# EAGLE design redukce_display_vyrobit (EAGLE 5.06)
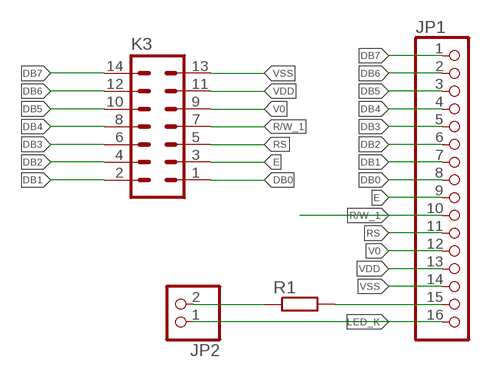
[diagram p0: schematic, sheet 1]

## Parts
JP1  PINHD-1X16  [1X16]
JP2  PINHD-1X2  [1X02]
K3  14V  [14V]
R1  R-EU_0207/10  [0207/10]

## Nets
DB0: JP1.8 K3.1
DB1: JP1.7 K3.2
DB2: JP1.6 K3.4
DB3: JP1.5 K3.6
DB4: JP1.4 K3.8
DB5: JP1.3 K3.10
DB6: JP1.2 K3.12
DB7: JP1.1 K3.14
E: JP1.9 K3.3
LED_K: JP1.16 JP2.1
N$1: JP2.2 R1.1
N$2: JP1.15 R1.2
R/W_1: JP1.10 K3.7
RS: JP1.11 K3.5
V0: JP1.12 K3.9
VDD: JP1.13 K3.11
VSS: JP1.14 K3.13

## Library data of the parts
JP1 = pinhead:PINHD-1X16: PIN HEADER
JP2 = pinhead:PINHD-1X2: PIN HEADER
K3 = con-harting-v:14V: CONNECTOR
R1 = rcl:R-EU_: RESISTOR, European symbol

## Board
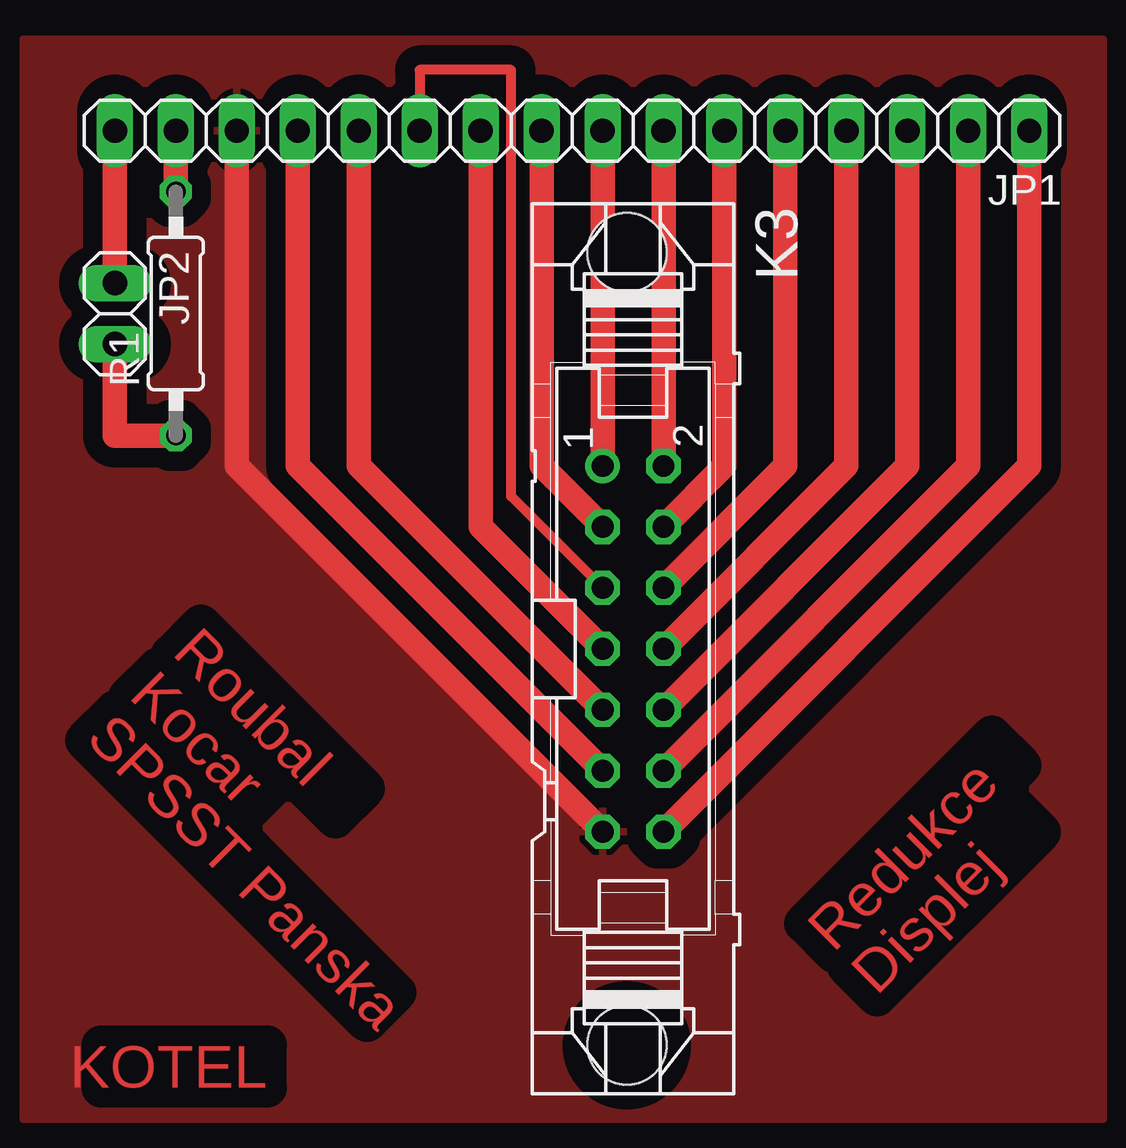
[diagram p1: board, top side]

No outline drawn. Coordinates in mm, seen from the top.
Copper layers (1*16): Top 0.035mm / dielectric 1.5mm / Bottom 0.035mm
Design rules "default": minimum track width 10mil, minimum drill 24mil, track to track 8mil, track to pad 8mil, pad to pad 8mil, via to via 8mil, smd to smd 8mil, copper to edge 40mil, drill to drill 8mil, minimum pad ring 10mil, minimum via ring 8mil, stop-mask expansion 4mil, vias tented up to drill 0mil, thermal gap 10mil

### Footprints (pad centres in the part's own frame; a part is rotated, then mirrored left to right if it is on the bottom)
1X16 = drill 1.016 long: 1 -19.05,0; 2 -16.51,0; 3 -13.97,0; 4 -11.43,0; 5 -8.89,0; 6 -6.35,0; 7 -3.81,0; 8 -1.27,0; 9 1.27,0; 10 3.81,0; 11 6.35,0; 12 8.89,0; 13 11.43,0; 14 13.97,0; 15 16.51,0; 16 19.05,0
1X02 = drill 1.016 long: 1 -1.27,0; 2 1.27,0
14V = drill 0.914 round: 1 -7.62,-1.27 | drill 0.914 octagon: 2 -7.62,1.27; 3 -5.08,-1.27; 4 -5.08,1.27; 5 -2.54,-1.27; 6 -2.54,1.27; 7 0,-1.27; 8 0,1.27; 9 2.54,-1.27; 10 2.54,1.27; 11 5.08,-1.27; 12 5.08,1.27; 13 7.62,-1.27; 14 7.62,1.27 | hole 3.302: 16.51,-0.254; -16.51,-0.254
0207/10 = drill 0.813 octagon: 1 -5.08,0; 2 5.08,0

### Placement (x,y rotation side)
JP1  22.86,-3.81 180 top
JP2  3.81,-11.43 270 top
K3  25.4,-25.4 270 top
R1  6.35,-11.43 90 top

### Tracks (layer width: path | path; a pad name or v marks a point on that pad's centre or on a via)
DB0
  Top 1.016: K3.1 JP1.8
DB1
  Top 1.016: K3.2 JP1.7
DB2
  Top 1.016: K3.4 29.21,-17.78 JP1.6
DB3
  Top 1.016: K3.6 31.75,-17.78 JP1.5
DB4
  Top 1.016: K3.8 34.29,-17.78 JP1.4
DB5
  Top 1.016: K3.10 36.83,-17.78 JP1.3
DB6
  Top 1.016: K3.12 39.37,-17.78 JP1.2
DB7
  Top 1.016: K3.14 41.91,-17.78 JP1.1
E
  Top 1.016: K3.3 21.59,-17.78 JP1.9
LED_K
  Top 1.016: JP1.16 JP2.1
N$1
  Top 1.016: R1.1 3.81,-16.51 JP2.2
N$2
  Top 1.016: R1.2 JP1.15
R/W_1
  Top 1.016: K3.7 19.05,-20.32 JP1.10
RS
  Top 0.406: K3.5 20.32,-19.05 20.32,-1.27 16.51,-1.27 JP1.11
V0
  Top 1.016: K3.9 13.97,-17.78 JP1.12
VDD
  Top 1.016: K3.11 11.43,-17.78 JP1.13
VSS
  Top 1.016: K3.13 8.89,-17.78 JP1.14
  pour Top (isolate 0.813): 0,0 45,0 45,-45 0,-45

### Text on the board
Top: Roubal | Kocar | SPSST Panska | Redukce | Displej | KOTEL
